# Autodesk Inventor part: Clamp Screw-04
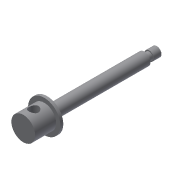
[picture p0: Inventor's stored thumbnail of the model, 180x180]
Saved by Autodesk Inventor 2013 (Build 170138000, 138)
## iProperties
Shininess: 77.0
Length Units: 11269
Angle Units: 11279
Time Units: 11290
Mass Units: 11283
Length Display Precision: 3
Angle Display Precision: 2
Created: 2002-02
Part Number: Clamp Screw-04
Document SubType Name: Modeling
Designer: ***
Density: 1 g/cm^3
Material: Generic
Density: 0.0
Volumn: 0.0
Area: 0.0
PropertySet Name: Model Information
Control State: 0
Master: False
Checked Out: False
Author: ***
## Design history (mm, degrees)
sketch "Sketch1"
  geometry: L1 (0, 140)-(5, 140); L2 (5, 140)-(5, 132); L3 (5, 132)-(4, 132); L4 (4, 132)-(4, 127); L5 (4, 127)-(6.5, 127); L6 (6.5, 127)-(6.5, 25); L7 (6.5, 25)-(17, 25); L8 (17, 25)-(17, 22); L9 (17, 22)-(12.5, 22); L10 (12.5, 22)-(12.5, 0); L11 (12.5, 0)-(0, 0); L12 (0, 0)-(0, 140)
  constraints: 24 end point, 10 parallel, 1 horizontal, 1 perpendicular
  dimensions: "d0" = 10 diameter of L2 L12; "d1" = 8 diameter of L4 L12; "d2" = 13 diameter of L6 L12; "d3" = 34 diameter of L7.end L12; "d4" = 25 diameter of L10 L12; "d5" = 3 distance from line of L7.end L9; "d6" = 8 distance of L1.end L2.end; "d7" = 13 vertical distance of L1.end L5.end; "d8" = 22 distance of L9.end L10.end; "d10" = 102 distance of L5.end L6.end
revolve "Revolution1" sketch "Sketch1" stored, may be unused: angle "d11" = 90 deg
sketch "Sketch3"
  geometry: L1 (-12.5, 0)-(12.5, 0) reference; C1 r 5 at (-0.113, 11)
  constraints: 1 centre point
  dimensions: "d13" = 10 diameter of C1; "d14" = 11 distance from line of L1 C1.centre
extrude "Extrusion1" cut sketch "Sketch3" stored distance "d15" = 10; taper "d16" = 0 deg
body "Solid1"
